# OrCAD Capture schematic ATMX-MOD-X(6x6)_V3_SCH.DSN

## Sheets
1 1. TITLE: title: TITLE; rev: 03; note: HB126
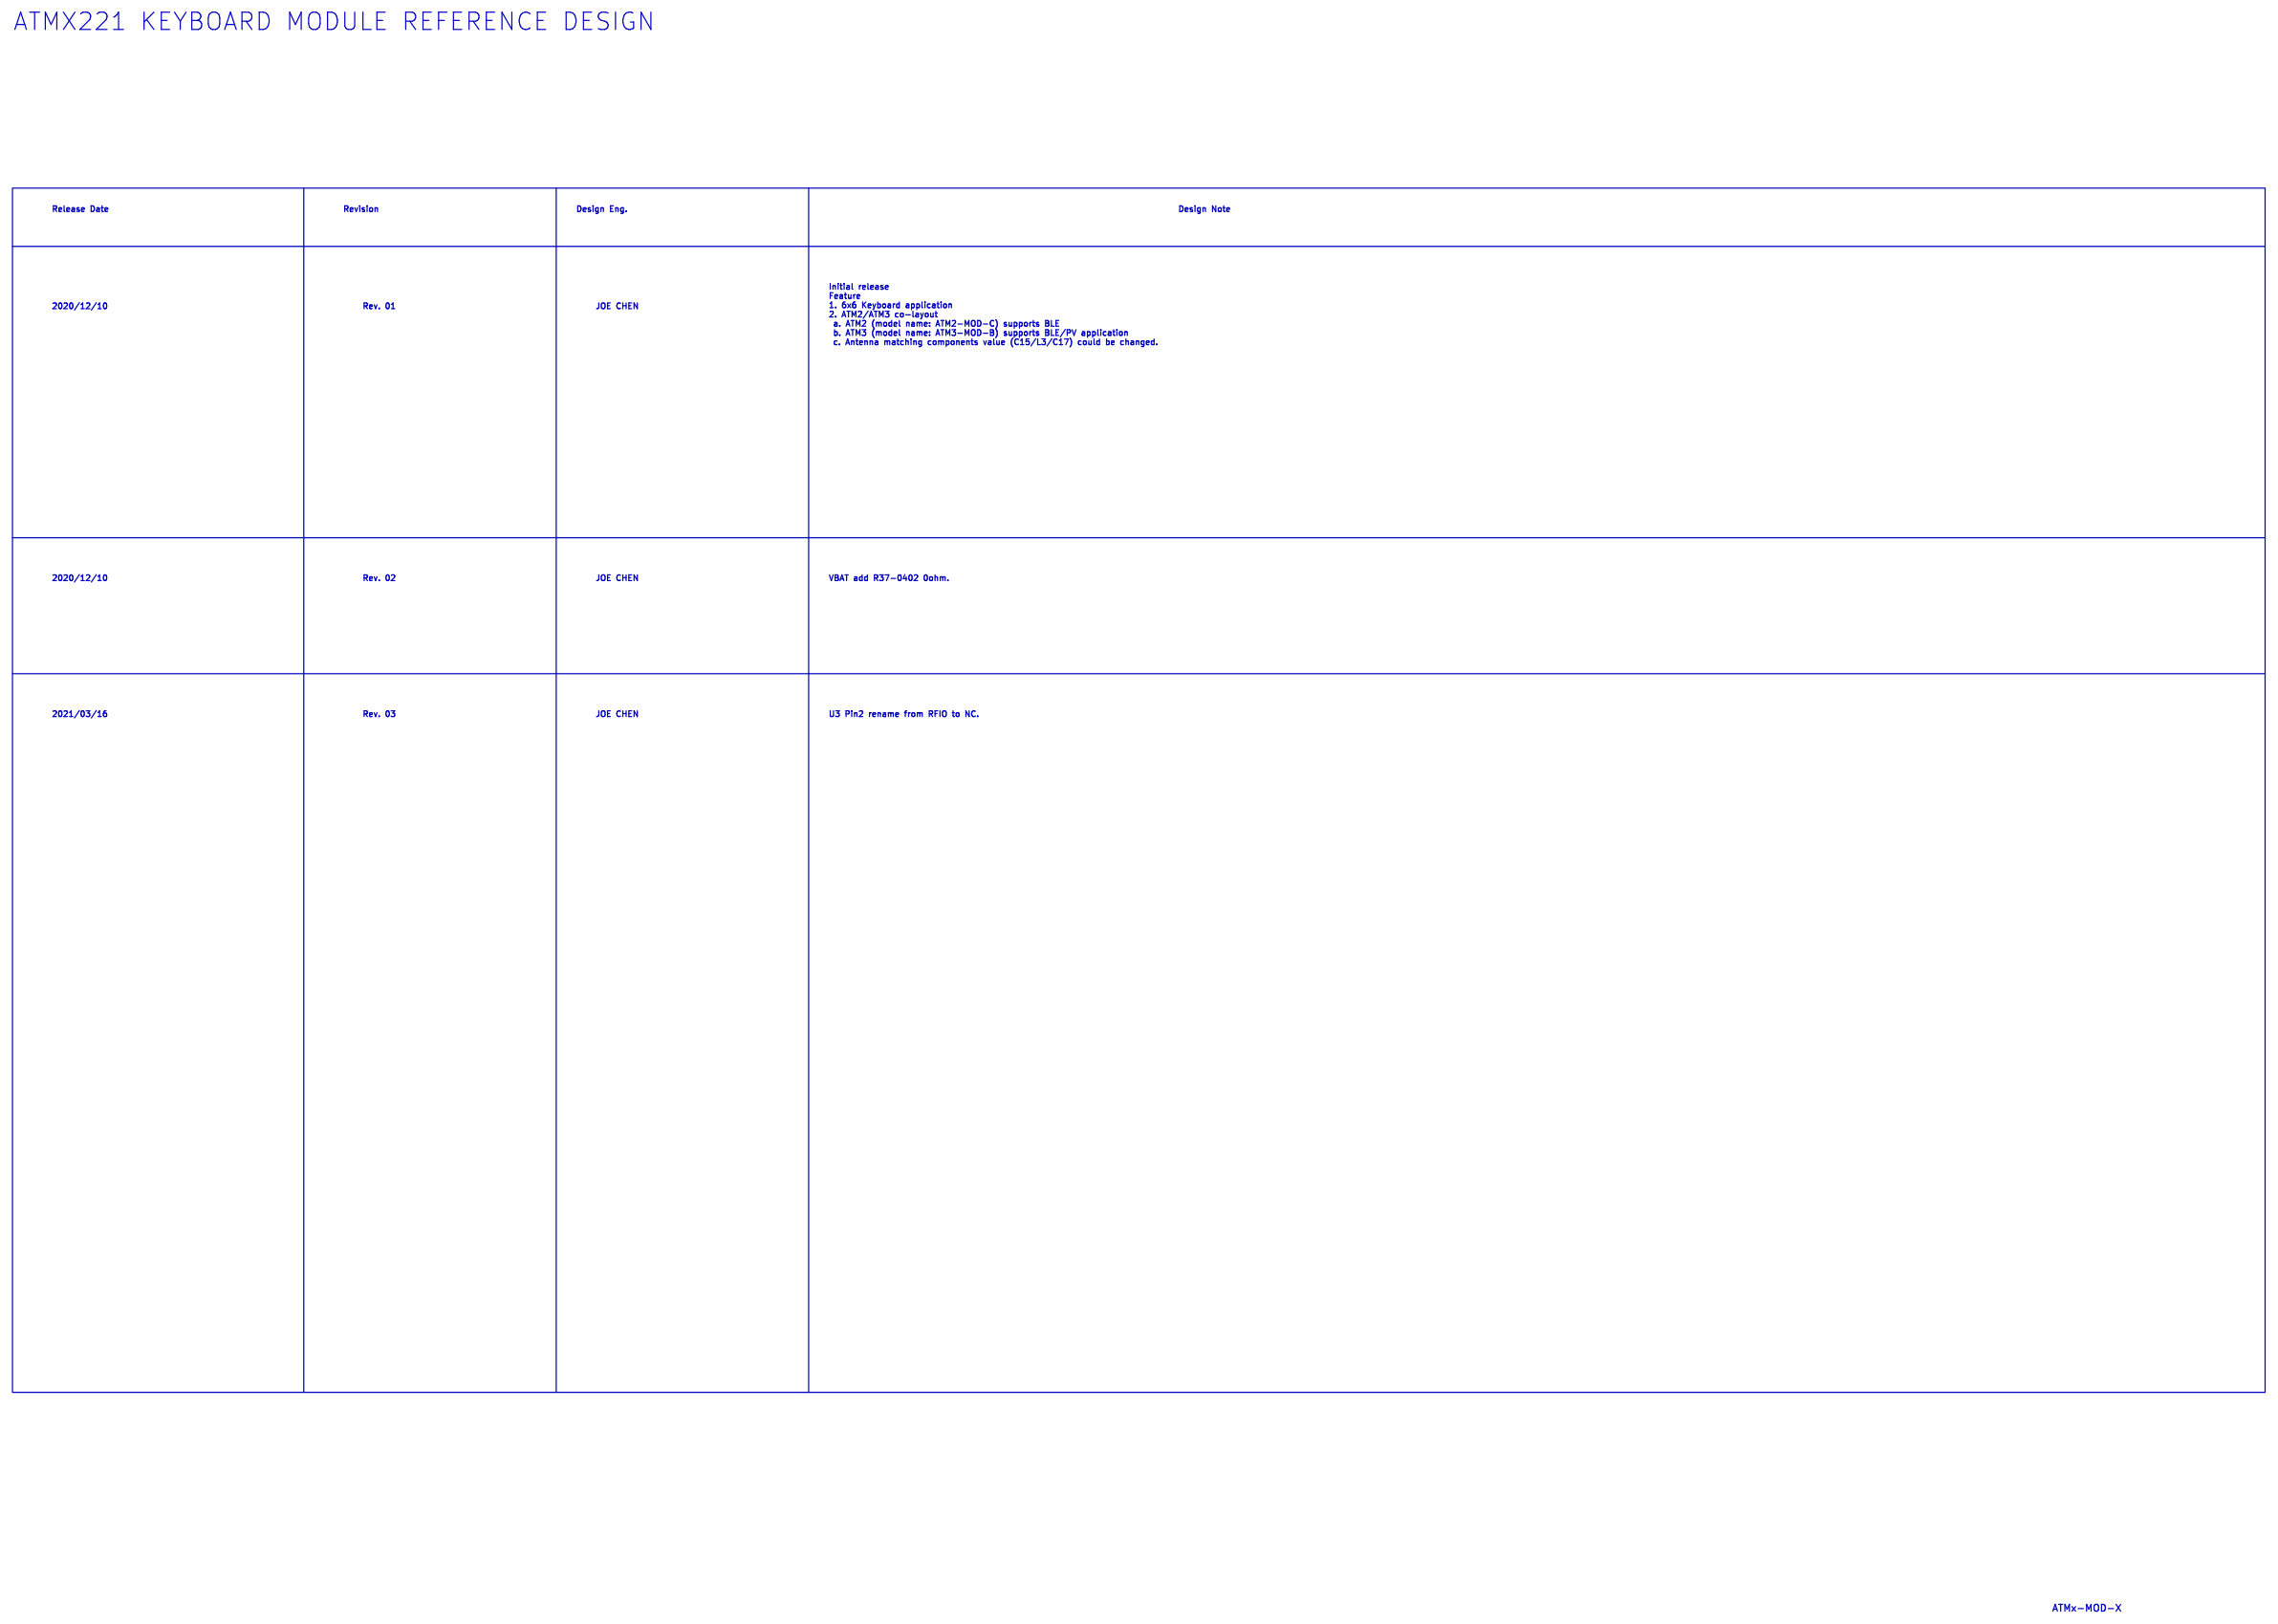
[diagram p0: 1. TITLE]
2 2. MODULE: size B; title: MODULE; note: Main
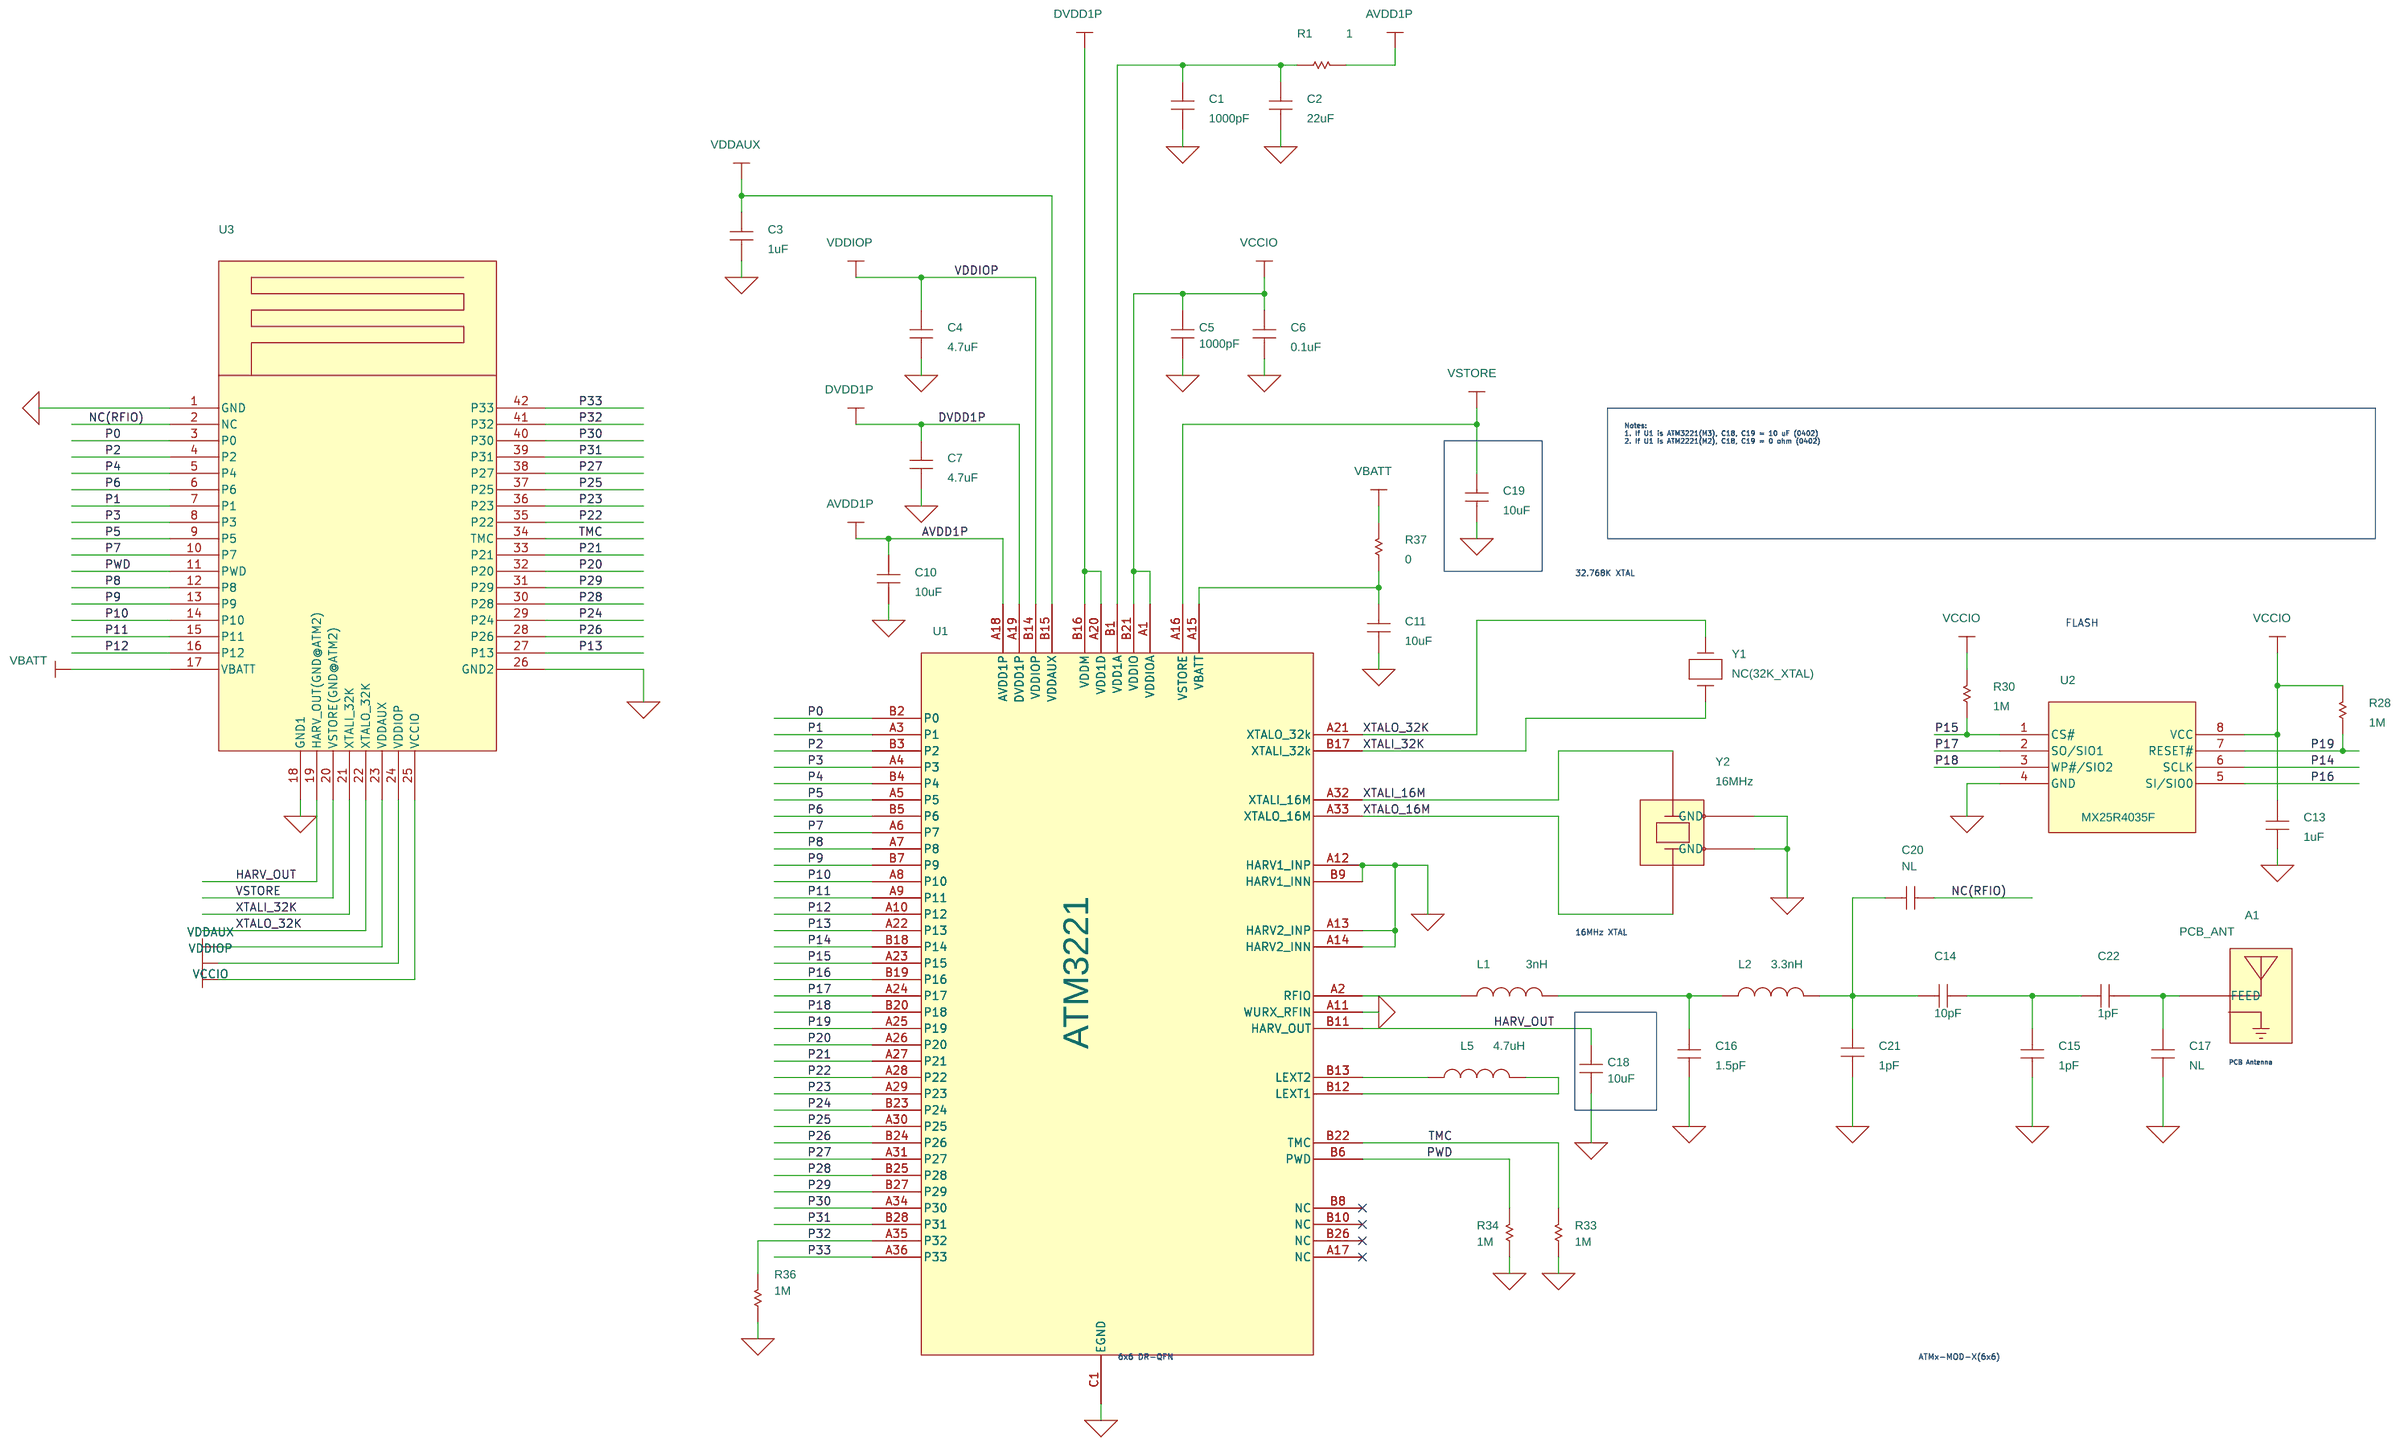
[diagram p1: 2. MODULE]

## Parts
A1  PCB_ANT  [ANTS1]
C1  1000pF  [L-0201-H0_33]
C2  22uF  [C-0603-H0_8]
C3  1uF  [C-0402-H0_5-CZ]
C4  4.7uF  [C-0402-H0_5-CZ]
C5  1000pF  [L-0201-H0_33]
C6  0.1uF  [C-0402-H0_5-CZ]
C7  4.7uF  [C-0402-H0_5-CZ]
C10  10uF  [C-0402-H0_5-CZ]
C11  10uF  [C-0402-H0_5-CZ]
C13  1uF  [C-0402-H0_5-CZ]
C14  10pF  [L-0201-H0_33]
C15  1pF  [L-0201-H0_33]
C16  1.5pF  [L-0201-H0_33]
C17  NL  [L-0201-H0_33]
C18  10uF  [C-0402-H0_5-CZ]
C19  10uF  [C-0402-H0_5-CZ]
C20  NL  [L-0201-H0_33]
C21  1pF  [L-0201-H0_33]
C22  1pF  [L-0201-H0_33]
L1  3nH  [L-0201-H0_33]
L2  3.3nH  [L-0201-H0_33]
L5  4.7uH  [IND-2016-2]
R1  1  [L-0201-H0_33]
R28  1M  [L-0201-H0_33]
R30  1M  [L-0201-H0_33]
R33  1M  [L-0201-H0_33]
R34  1M  [L-0201-H0_33]
R36  1M  [L-0201-H0_33]
R37  0  [0402]
U1  ATM3221  [DRQFN6X6-64-0.5]
U2  MX25R4035F  [USON-8-2X3MM]
U3  ATMx-MOD_6x6  [ATMx-MOD_6x6]
Y1  NC(32K_XTAL)  [XTAL-SMD2-2.0X1.2MM]
Y2  16MHz  [XTAL-SMD4-2_5X2_0-H0_65_SMALL]

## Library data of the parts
A1 = ANT-FEED-GND_0: PCB, Antenna For BCM920707EMB; Assembly Instructions: DO NOT INSTALL; BRCMPN: OPEN; Buy Instructions: DO NOT BUY; Critical: Y; Description 2: No_Physical_Part; Device File: ANTENNA-124865-0000_01; Vendor: NA; Vendor PN: NA
C1 C5 = SMALL_CAP: MF: MURATA; Part Number: GRM0335C1E102JA01
C2 = SMALL_CAP: MF: MURATA; Part Number: GRM188R61A226ME15D
C3 C13 = SMALL_CAP: MF: MURATA; Part Number: GRM155R61C105KA12D
C4 C7 = SMALL_CAP: MF: MURATA; Part Number: GRM155R60J475ME47D
C6 = SMALL_CAP: MF: MURATA; Part Number: GRM155R71H104KE14D
C10 C11 C18 C19 = SMALL_CAP: MF: MURATA; Part Number: GRM155R60J106ME44D
C14 = SMALL_CAP: MF: MURATA; Part Number: GRM0335C1H100GA01
C15 C21 C22 = SMALL_CAP: MF: MURATA; Part Number: GRM0335C1H1R0BA01
C16 = SMALL_CAP: MF: MURATA; Part Number: GRM0335C1H1R5BA01
C17 C20 = SMALL_CAP
L1 = INDUCTOR: MF: MURATA; Part Number: LQP03TN3N0B02D
L2 = INDUCTOR: MF: MURATA; Part Number: LQP03TN3N3B02D
L5 = INDUCTOR: MF: MURATA; Part Number: LQM21PN4R7MGRD
R1 = SMALL_R1: MF: TA-I; Part Number: RM02JTN1R0
R28 R30 R33 R34 R36 = SMALL_R1: MF: TA-I; Part Number: RM02JTN105
R37 = SMALL_R1: MF: TA-I
U1 = SYDNEY_2_1.0_DRQFN_6X6: MF: ATMOSIC
U2 = LM258DRG3_0: MF: MICRONIX; Part Number: MX25R4035FZUIL0
U3 = ATMx-MOD_5
Y1 = XTAL: MF: NC(MICRO CRYSTAL); Part Number: NC(CM8V-T1A-32.768KHZ-7PF-20PPM-TA-QC)
Y2 = XTAL-1G3G: XTL,FXD,SMT,24.000MHz,10/10PPM,2x1.6mm; Critical: Y; Description 2: 8pF,FUND,100mW; Height: 0.9000 mm; MF: ECS Inc.; Vendor: TXC; Vendor PN: 8Y24070015

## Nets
AVDD1P: C10.1 R1.2 U1.A18(AVDD1P)
DVDD1P: C7.1 U1.A19(DVDD1P) U1.A20(VDD1D) U1.B16(VDDM)
GND_SIGNAL: C1.2 C2.2 C3.2 C4.2 C5.2 C6.2 C7.2 C10.2 C11.2 C13.1 C15.1 C16.1 C17.1 C18.2 C19.2 C21.2 R33.1 R34.1 R36.1 U1.A11(WURX_RFIN) U1.A12(HARV1_INP) U1.A13(HARV2_INP) U1.A14(HARV2_INN) U1.B9(HARV1_INN) U1.C1(EGND) U2.4(GND) U3.1(GND) U3.18(GND1) U3.26(GND2) Y2.2(GND) Y2.4(GND)
VBATT: R37.2 U3.17(VBATT)
VCCIO: C5.1 C6.1 C13.2 R28.1 R30.1 U1.A1(VDDIOA) U1.B21(VDDIO) U2.8(VCC) U3.25(VCCIO)
VDDAUX: C3.1 U1.B15(VDDAUX) U3.23(VDDAUX)
VDDIOP: C4.1 U1.B14(VDDIOP) U3.24(VDDIOP)
HARV_OUT: C18.1 U1.B11(HARV_OUT) U3.19(HARV_OUT(GND@ATM2))
NC(RFIO): C20.1 U3.2(NC)
P0: U1.B2(P0) U3.3(P0)
P1: U1.A3(P1) U3.7(P1)
P2: U1.B3(P2) U3.4(P2)
P3: U1.A4(P3) U3.8(P3)
P4: U1.B4(P4) U3.5(P4)
P5: U1.A5(P5) U3.9(P5)
P6: U1.B5(P6) U3.6(P6)
P7: U1.A6(P7) U3.10(P7)
P8: U1.A7(P8) U3.12(P8)
P9: U1.B7(P9) U3.13(P9)
P10: U1.A8(P10) U3.14(P10)
P11: U1.A9(P11) U3.15(P11)
P12: U1.A10(P12) U3.16(P12)
P13: U1.A22(P13) U3.27(P13)
P14: U1.B18(P14) U2.6(SCLK)
P15: R30.2 U1.A23(P15) U2.1(CS#)
P16: U1.B19(P16) U2.5(SI/SIO0)
P17: U1.A24(P17) U2.2(SO/SIO1)
P18: U1.B20(P18) U2.3(WP#/SIO2)
P19: R28.2 U1.A25(P19) U2.7(RESET#)
P20: U1.A26(P20) U3.32(P20)
P21: U1.A27(P21) U3.33(P21)
P22: U1.A28(P22) U3.35(P22)
P23: U1.A29(P23) U3.36(P23)
P24: U1.B23(P24) U3.29(P24)
P25: U1.A30(P25) U3.37(P25)
P26: U1.B24(P26) U3.28(P26)
P27: U1.A31(P27) U3.38(P27)
P28: U1.B25(P28) U3.30(P28)
P29: U1.B27(P29) U3.31(P29)
P30: U1.A34(P30) U3.40(P30)
P31: U1.B28(P31) U3.39(P31)
P32: R36.2 U1.A35(P32) U3.41(P32)
P33: U1.A36(P33) U3.42(P33)
PWD: R34.2 U1.B6(PWD) U3.11(PWD)
TMC: R33.2 U1.B22(TMC) U3.34(TMC)
VSTORE: C19.1 U1.A16(VSTORE) U3.20(VSTORE(GND@ATM2))
XTALI_16M: U1.A32(XTALI_16M) Y2.1
XTALI_32K: U1.B17(XTALI_32k) U3.21(XTALI_32K) Y1.1
XTALO_16M: U1.A33(XTALO_16M) Y2.3
XTALO_32K: U1.A21(XTALO_32k) U3.22(XTALO_32K) Y1.2
N16434369: L1.1 U1.A2(RFIO)
N16438070: C1.1 C2.1 R1.1 U1.B1(VDD1A)
N16728527: C11.1 R37.1 U1.A15(VBATT)
N16728682: L5.2 U1.B12(LEXT1)
N16790979: L5.1 U1.B13(LEXT2)
N16833412: C16.2 L1.2 L2.1
N16833422: C14.2 C20.2 C21.1 L2.2
N16869838: C14.1 C15.2 C22.1
N16869944: A1.1(FEED) C17.2 C22.2

Not connected (* = marked no-connect by the designer): U1 A17(NC)* B8(NC)* B10(NC)* B26(NC)*

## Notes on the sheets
sheet 1
- ATMX221 KEYBOARD MODULE REFERENCE DESIGN
- Release Date
- Revision
- Design Eng.
- Design Note
- Initial release
  Feature
  1. 6x6 Keyboard application
  2. ATM2/ATM3 co-layout
   a. ATM2 (model name: ATM2-MOD-C) supports BLE
   b. ATM3 (model name: ATM3-MOD-B) supports BLE/PV application
   c. Antenna matching components value (C15/L3/C17) could be changed.
- 2020/12/10
- Rev. 01
- JOE CHEN
- 2020/12/10
- Rev. 02
- JOE CHEN
- VBAT add R37-0402 0ohm.
- 2021/03/16
- Rev. 03
- JOE CHEN
- U3 Pin2 rename from RFIO to NC.
- ATMx-MOD-X
sheet 2
- Notes:
  1. If U1 is ATM3221(M3), C18, C19 = 10 uF (0402)
  2. If U1 is ATM2221(M2), C18, C19 = 0 ohm (0402)
- 32.768K XTAL
- FLASH
- 16MHz XTAL
- PCB Antenna
- 6x6 DR-QFN
- ATMx-MOD-X(6x6)
